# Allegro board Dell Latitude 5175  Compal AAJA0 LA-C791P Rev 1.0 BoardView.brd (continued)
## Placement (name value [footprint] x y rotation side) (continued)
Q18  AO7400_SC-70-3  [AO7404_SC70-3]  35.98 109.62 270 bottom
Q20  -  [MMBT3904WH_SOT323-3]  20.62 69.22 180 bottom
Q21  -  [MMBT3904WH_SOT323-3]  25.48 14.12 0 bottom
Q22  -  [DMP3099L-7_SOT23-3]  208.5 107.22 180 bottom
Q23  DII-DMN65D8LW-7  [SSM3K7002FU_SC70-3]  205.1 104.07 180 bottom
QA2  -  [DMN2400UV-7_SOT-563-6]  13.23 138.87 180 bottom
QT1  -  [DMN2400UV-7_SOT-563-6]  35.07 56.77 180 top
R1  10K_0201_1%  [R_0201]  208.04 143.21 90 top
R2  2.2K_0201_5%  [R_0201]  198.02 143.13 90 top
R3  100K_0201_5%  [R_0201]  198.65 143.13 90 top
R4  0_0402_5%  [R0402_0OHM]  202.67 143.14 0 top
R5  100K_0402_5%  [R_0402]  210.4 142.42 180 top
R6  0_0402_5%  [R_0402]  203.58 141.93 180 top
R7  0_0201_5%  [R_0201]  209.37 141.59 270 top
R8  0_0402_5%  [R_0402]  203.58 140.91 180 top
R9  33_0201_1%  [R_0201]  49.76 140.67 270 top
R10  10K_0402_5%  [R_0402]  48.44 139.61 90 top
R11  0_0402_5%  [R_0402]  203.56 139.87 180 top
R12  0_0201_5%  [R0201_0OHM]  49.17 139.41 0 top
R13  0_0402_5%  [R_0402]  203.56 138.98 180 top
R14  0_0201_5%  [R0201_0OHM]  210.63 138.58 90 top
R15  0_0603_5%  [R0603_0OHM]  46.63 138.5 180 top
R16  0_0402_5%  [R0402_0OHM]  194.18 138.93 270 top
R17  0_0402_5%  [R_0402]  195.07 138.93 270 top
R18  33_0201_1%  [R_0201]  49.78 138.72 270 top
R19  0_0201_5%  [R0201_0OHM]  211.21 137.89 90 top
R20  0_0201_5%  [R0201_0OHM]  210.62 137.27 90 top
R21  1K_0201_5%  [R_0201]  6.73 136.96 90 top
R22  100K_0201_5%  [R_0201]  192.81 136.48 90 top
R23  0_0402_5%  [R0402_0OHM]  191.92 136.79 270 top
R24  10K_0402_5%  [R_0402]  197.46 136.29 180 top
R25  33_0201_1%  [R_0201]  49.81 135.75 90 top
R26  10K_0201_5%  [R_0201]  57.2 135.42 90 top
R27  10K_0201_1%  [R_0201]  211.65 135.52 180 top
R28  1M_0201_5%  [R_0201]  50.04 134.83 180 top
R29  0_0402_5%  [R_0402]  206.27 135.24 270 top
R30  0_0402_5%  [R_0402]  207.16 135.24 270 top
R31  10K_0201_1%  [R_0201]  207.92 135.08 270 top
R32  0_0402_5%  [R_0402]  53.66 134.66 0 top
R33  0_0402_5%  [R_0402]  191.92 134.13 90 top
R34  100K_0201_5%  [R_0201]  48.79 134.27 90 top
R35  0_0402_5%  [R0402_0OHM]  43.23 134.38 180 top
R36  0_0603_5%  [R0603_0OHM]  56.72 134.6 270 top
R37  0_0402_5%  [R_0402]  53.66 133.8 0 top
R38  100K_0201_5%  [R_0201]  190.33 133.31 90 top
R39  0_0402_5%  [R_0402]  53.66 132.93 0 top
R40  100K_0201_5%  [R_0201]  119.93 132.34 0 top
R41  100K_0201_5%  [R_0201]  121.73 132.32 180 top
R42  100K_0201_5%  [R_0201]  149.15 132.3 180 top
R43  0_0402_5%  [R0402_0OHM]  209.6 132.3 0 top
R44  0_0402_5%  [R0402_0OHM]  147.84 132.2 180 top
R45  0_0402_5%  [R0402_0OHM]  140.18 132.18 0 top
R46  0_0402_5%  [R_0402]  53.66 132.07 0 top
R49  100K_0201_5%  [R_0201]  149.15 131.66 180 top
R50  560K_0402_5%  [R_0402]  142.13 131.59 0 top
R51  0_0201_5%  [R_0201]  209.74 131.56 0 top
R52  10K_0201_1%  [R_0201]  205.13 131.19 90 top
R53  0_0402_5%  [R0402_0OHM]  24.82 131.19 0 top
R54  10K_0402_5%  [R_0402]  26.56 131.19 0 top
R55  0_0603_5%  [R0603_0OHM]  124.46 131.16 180 top
R56  0_0402_5%  [R0402_0OHM]  120.57 131.56 270 top
R57  0_0603_5%  [R0603_0OHM]  129.86 130.8 0 top
R58  0_0603_5%  [R0603_0OHM]  145.26 129.86 90 top
R59  0_0603_5%  [R0603_0OHM]  144.06 129.85 90 top
R60  100K_0201_5%  [R_0201]  197.74 130.66 270 top
R61  10K_0201_5%  [R_0201]  198.4 130.66 270 top
R62  680_0201_5%  [R_0201]  122.31 130.04 0 top
R63  100K_0201_5%  [R_0201]  108.24 129.99 180 top
R64  8.2K_0201_1%  [R_0201]  86.42 129.96 0 top
R65  470K_0402_5%  [R_0402]  143.01 129.83 180 top
R66  10_0201_1%  [R_0201]  87.64 129.37 90 top
R67  100K_0201_5%  [R_0201]  49.12 129.34 90 top
R68  75_0402_5%  [R_0402]  191.3 129.62 180 top
R69  0_0402_5%  [R_0402]  120.13 129.57 0 top
R70  0_0402_5%  [R0402_0OHM]  30.3 129.53 180 top
R71  8.2K_0201_1%  [R_0201]  87.01 129.4 180 top
R72  1M_0402_5%  [R_0402]  137.13 128.79 180 top
R73  0_0402_5%  [R_0402]  30.3 128.64 180 top
R74  8.2K_0201_1%  [R_0201]  82.55 128.91 270 top
R75  10_0201_1%  [R_0201]  83.16 128.32 90 top
R76  8.2K_0201_1%  [R_0201]  83.77 128.32 90 top
R77  24.9_0201_1%  [R_0201]  85.75 128.69 270 top
R78  0_0402_5%  [R0402_0OHM]  113.74 127.85 90 top
R79  0_0402_5%  [R0402_0OHM]  114.76 127.85 90 top
R80  0_0402_5%  [R0402_0OHM]  115.67 127.85 90 top
R81  0_0402_5%  [R0402_0OHM]  116.69 127.85 90 top
R82  0_0402_5%  [R0402_0OHM]  117.63 127.85 90 top
R83  0_0402_5%  [R0402_0OHM]  118.64 127.85 90 top
R84  0_0201_5%  [R_0201]  140.78 128.06 180 top
R85  100K_0201_5%  [R_0201]  150.04 127.96 0 top
R86  0_0402_5%  [R0402_0OHM]  96.98 127.83 0 top
R87  0_0201_5%  [R0201_0OHM]  139.6 128.09 270 top
R88  0_0402_5%  [R_0402]  92.96 127.8 0 top
R89  0_0603_5%  [R0603_0OHM]  126.47 127.68 180 top
R93  0_0603_5%  [R0603_0OHM]  209.09 127.32 0 top
R94  100K_0201_5%  [R_0201]  140.18 126.85 90 top
R95  100K_0201_5%  [R_0201]  140.79 126.85 90 top
R96  0_0402_5%  [R0402_0OHM]  96.98 126.96 0 top
R97  0_0402_5%  [R_0402]  92.96 126.93 0 top
R98  0_0603_5%  [R0603_0OHM]  105.7 126.79 180 top
R99  8.2K_0201_5%  [R_0201]  132.93 126.79 0 top
R101  220K_0201_5%  [R_0201]  44.59 126.69 0 top
R102  24.9_0201_1%  [R_0201]  83.85 126.66 180 top
R103  100_0402_5%  [R_0402]  26.72 126.6 180 top
R104  220K_0201_5%  [R_0201]  47.28 126.58 0 top
R105  100K_0201_5%  [R_0201]  204.1 126.41 0 top
R107  0_0402_5%  [R0402_0OHM]  52.5 126.58 270 top
R108  0_0603_5%  [R0603_0OHM]  108.29 125.36 0 top
R109  0_0603_5%  [R0603_0OHM]  125.53 125.97 270 top
R110  0_0603_5%  [R0603_0OHM]  126.75 125.96 270 top
R111  100K_0201_5%  [R_0201]  204.1 125.26 0 top
R114  8.2K_0201_5%  [R_0201]  132.7 124.32 0 top
R115  0_0603_5%  [R0603_0OHM]  209.05 124.3 0 top
R116  0_0603_5%  [R0603_0OHM]  148.02 123.4 90 top
R117  0_0603_5%  [R0603_0OHM]  129.11 124.68 270 top
R118  8.2K_0201_1%  [R_0201]  90.86 123.9 270 top
R119  8.2K_0201_1%  [R_0201]  91.44 123.32 90 top
R120  4.99_0402_1%  [R_0402]  87.91 123.03 90 top
R121  0_0402_5%  [R0402_0OHM]  54.33 123.64 270 top
R123  0_0603_5%  [R0603_0OHM]  146.82 123.01 180 top
R124  1K_0201_5%  [R_0201]  7.54 122.75 180 top
R125  24.9_0201_1%  [R_0201]  89.51 122.05 90 top
R126  0_0402_5%  [R_0402]  127.81 121.4 90 top
R132  10K_0402_5%  [R_0402]  213.22 120.35 270 top
R133  10K_0402_5%  [R_0402]  210.51 120.34 270 top
R134  10K_0402_5%  [R_0402]  211.43 120.34 270 top
R135  10K_0402_5%  [R_0402]  212.32 120.34 270 top
R136  10K_0402_5%  [R_0402]  214.13 120.34 270 top
R137  10K_0402_5%  [R_0402]  208.6 120.32 270 top
R138  10K_0402_5%  [R_0402]  209.61 120.32 270 top
R139  0_0402_5%  [R_0402]  124.07 117.87 90 top
R140  0_0402_5%  [R0402_0OHM]  28.93 114.76 0 top
R141  0_0402_5%  [R_0402]  28.93 113.85 0 top
R142  0_0603_5%  [R0603_0OHM]  24.79 112.61 90 top
R143  0_0402_5%  [R0402_0OHM]  30.82 113.1 0 top
R144  100K_0201_5%  [R_0201]  29.98 111.8 180 top
R145  100K_0201_5%  [R_0201]  29.98 111.24 180 top
R146  10K_0402_5%  [R_0402]  214.87 110.95 270 top
R147  10K_0402_5%  [R_0402]  215.86 110.95 270 top
R148  10K_0402_5%  [R_0402]  216.85 110.95 270 top
R149  0_0603_5%  [R0603_0OHM]  25.07 110.3 180 top
R150  220K_0201_5%  [R_0201]  117.06 109.29 180 top
R151  10K_0402_5%  [R_0402]  213.86 108.24 90 top
R152  10K_0402_5%  [R_0402]  214.87 108.21 90 top
R153  10K_0402_5%  [R_0402]  215.86 108.21 90 top
R154  10K_0402_5%  [R_0402]  216.85 108.21 90 top
R155  100K_0201_5%  [R_0201]  150.29 107.48 0 top
R156  10K_0201_5%  [R_0201]  139.78 107.39 270 top
R157  10K_0201_5%  [R_0201]  140.33 107.39 270 top
R158  10K_0201_5%  [R_0201]  140.97 107.39 270 top
R159  10K_0201_5%  [R_0201]  141.6 107.39 270 top
R160  0_0603_5%  [R0603_0OHM]  37.29 106.3 90 top
R161  0_0603_5%  [R0603_0OHM]  34.34 106.28 90 top
R162  100K_0201_5%  [R_0201]  215.8 106.89 270 top
R163  0_0402_5%  [R0402_0OHM]  131.19 105.81 180 top
R164  0_0402_5%  [R0402_0OHM]  170.54 105.7 0 top
R165  0_0603_5%  [R0603_0OHM]  46.55 104.87 180 top
R166  0_0402_5%  [R_0402]  196.99 104.6 270 top
R167  100K_0201_5%  [R_0201]  51.93 103.57 180 top
R168  220K_0201_5%  [R_0201]  102.81 102.8 90 top
R169  100K_0201_5%  [R_0201]  51.93 102.99 180 top
R170  0_0402_5%  [R_0402]  77.24 102.61 180 top
R171  0_0402_5%  [R0402_0OHM]  68.76 102.33 0 top
R172  10K_0201_5%  [R_0201]  137.52 102.03 90 top
R173  10K_0201_5%  [R_0201]  138.1 102.03 90 top
R174  0_0603_5%  [R0603_0OHM]  151.76 102.85 270 top
R175  0_0402_5%  [R_0402]  51.98 101.58 180 top
R176  0_0402_5%  [R0402_0OHM]  68.76 101.44 0 top
R177  0_0402_5%  [R_0402]  212.42 101.39 0 top
R178  0_0402_5%  [R_0402]  76.35 101.72 270 top
R179  100K_0201_5%  [R_0201]  36.98 100.85 90 top
R180  0_0402_5%  [R_0402]  35.36 100.68 90 top
R181  0_0402_5%  [R0402_0OHM]  36.25 100.68 90 top
R182  0_0603_5%  [R0603_0OHM]  136.82 101.13 0 top
R183  0_0603_5%  [R0603_0OHM]  47.23 101.08 0 top
R184  100K_0201_5%  [R_0201]  77.09 101.37 270 top
R185  0_0402_5%  [R_0402]  51.98 100.72 180 top
R186  100K_0201_5%  [R_0201]  69.2 100.7 0 top
R187  0_0603_5%  [R0603_0OHM]  211.1 101.32 270 top
R188  10K_0402_5%  [R_0402]  212.42 100.5 0 top
R189  0_0402_5%  [R_0402]  202.59 100.5 270 top
R190  0_0201_5%  [R0201_0OHM]  181.51 99.99 0 top
R191  0_0201_5%  [R0201_0OHM]  181.51 99.35 0 top
R192  0_0603_5%  [R0603_0OHM]  213.26 99.49 270 top
R193  0_0402_5%  [R0402_0OHM]  195.61 98.72 0 top
R194  0_0201_5%  [R0201_0OHM]  170.9 98.62 0 top
R195  100K_0402_5%  [R_0402]  209.07 98.97 270 top
R196  0_0402_5%  [R_0402]  210.08 98.97 270 top
R197  10K_0402_5%  [R_0402]  210.97 98.97 270 top
R198  100K_0402_5%  [R_0402]  214.3 98.95 270 top
R199  100K_0402_5%  [R_0402]  215.19 98.95 270 top
R200  100K_0402_5%  [R_0402]  216.08 98.95 270 top
R201  0_0201_5%  [R0201_0OHM]  170.9 98.01 0 top
R202  10K_0402_5%  [R_0402]  25.09 82.18 0 top
R203  10K_0402_5%  [R_0402]  26.9 82.18 0 top
R204  10K_0402_5%  [R_0402]  25.09 81.19 0 top
R205  10K_0402_5%  [R_0402]  26.87 81.19 0 top
R206  10K_0402_5%  [R_0402]  25.09 80.2 0 top
R207  10K_0402_5%  [R_0402]  26.87 80.2 0 top
R208  10K_0402_5%  [R_0402]  25.09 79.26 0 top
R209  4.99K_0201_1%  [R_0201]  27.89 78.84 90 top
R210  100K_0201_5%  [R_0201]  41.95 76.09 0 top
R212  100K_0402_5%  [R_0402]  25.12 70.3 90 top
R213  10K_0402_5%  [R_0402]  26.7 70.3 90 top
R214  10K_0402_5%  [R_0402]  27.56 70.3 90 top
R217  0_0603_5%  [R0603_0OHM]  37.3 71.1 180 top
R218  4.7K_0402_5%  [R_0402]  43.74 64.73 180 top
R219  4.7K_0402_5%  [R_0402]  34.82 64.68 270 top
R220  0_0402_5%  [R_0402]  43.74 63.85 180 top
R221  4.7K_0402_5%  [R_0402]  43.74 62.96 180 top
R222  4.7K_0402_5%  [R_0402]  33.93 62.85 0 top
R223  4.7K_0402_5%  [R_0402]  33.06 62.87 270 top
R224  4.7K_0402_5%  [R_0402]  43.74 62.07 180 top
R225  4.7K_0402_5%  [R_0402]  33.93 61.94 0 top
R226  4.7K_0402_5%  [R_0402]  43.74 61.18 180 top
R227  4.7K_0402_5%  [R_0402]  33.93 61.04 0 top
R228  4.7K_0402_5%  [R_0402]  43.74 60.29 180 top
R229  4.7K_0402_5%  [R_0402]  33.93 60.15 0 top
R230  4.7K_0402_5%  [R_0402]  43.74 59.4 180 top
R231  0_0402_5%  [R0402_0OHM]  33.93 59.26 0 top
R232  4.7K_0402_5%  [R_0402]  43.74 58.51 180 top
R233  0_0201_5%  [R_0201]  34.56 58.26 0 top
R234  0_0201_5%  [R_0201]  36.39 58.26 180 top
R235  4.99K_0201_1%  [R_0201]  37.61 57.77 270 top
R236  0_0201_5%  [R0201_0OHM]  38.2 57.19 90 top
R237  0_0201_5%  [R0201_0OHM]  38.77 57.19 90 top
R238  100K_0201_5%  [R_0201]  35.24 57.51 180 top
R239  4.7K_0201_5%  [R_0201]  43.41 56.96 180 top
R240  100K_0402_5%  [R_0402]  26.94 66.25 0 top
R241  1M_0402_5%  [R_0402]  29.6 66.25 180 top
R242  0_0402_5%  [R0402_0OHM]  32.99 48.26 90 top
R243  10K_0402_5%  [R_0402]  31.38 64.9 180 top
R244  4.7K_0201_5%  [R_0201]  35.6 54.27 270 top
R245  100K_0402_5%  [R_0402]  23.71 60.95 90 top
R246  4.7K_0201_5%  [R_0201]  43.21 50.95 0 top
R247  100K_0402_5%  [R_0402]  39.8 50.82 180 top
R248  0_0402_5%  [R_0402]  22.82 60.95 90 top
R249  22.1K_0402_1%  [R_0402]  30.81 61.8 0 top
R250  0_0201_5%  [R0201_0OHM]  37.58 50.49 0 top
R251  4.7K_0201_5%  [R_0201]  43.21 50.39 0 top
R252  0_0402_5%  [R_0402]  21.93 60.95 90 top
R253  10K_0402_5%  [R_0402]  42.42 49.7 180 top
R254  0_0402_5%  [R0402_0OHM]  35.08 47.74 270 top
R255  0_0402_5%  [R0402_0OHM]  40.3 48.73 90 top
R256  93.1K_0402_1%  [R_0402]  38.53 48.72 90 top
R257  0_0402_5%  [R0402_0OHM]  39.42 48.72 90 top
R258  15K_0402_1%  [R_0402]  36.7 48.7 90 top
R259  0_0402_5%  [R_0402]  37.58 48.7 90 top
R260  0_0402_5%  [R_0402]  35.82 48.7 90 top
R261  10K_0402_5%  [R_0402]  29.62 42.34 270 top
R262  10K_0402_5%  [R_0402]  30.51 41.43 90 top
R263  10K_0402_5%  [R_0402]  42.42 48.81 180 top
R264  0_0402_5%  [R0402_0OHM]  30.52 40.55 180 top
R265  0_0402_5%  [R0402_0OHM]  31.81 46.65 270 top
R266  0_0402_5%  [R0402_0OHM]  32.7 46.65 270 top
R267  4.7K_0201_5%  [R_0201]  42.15 44.9 180 top
R268  10K_0402_5%  [R_0402]  39.49 45.19 270 top
R269  0_0402_5%  [R0402_0OHM]  29.67 45.28 270 top
R270  0_0402_5%  [R0402_0OHM]  30.53 45.28 270 top
R271  4.7K_0201_5%  [R_0201]  42.15 45.48 180 top
R272  4.7K_0201_5%  [R_0201]  32.49 44.05 90 top
R273  4.7K_0201_5%  [R_0201]  31.71 44.03 90 top
R274  0_0402_5%  [R_0402]  42.01 44.14 180 top
R275  10K_0402_5%  [R_0402]  43.08 45.07 270 top
R276  0_0402_5%  [R_0402]  29.6 39.66 0 top
R277  0_0402_5%  [R_0402]  29.6 38.78 0 top
R278  0_0402_5%  [R0402_0OHM]  32.26 41.75 0 top
R279  0_0402_5%  [R_0402]  30.52 37.89 180 top
R280  0_0402_5%  [R0402_0OHM]  32.26 40.86 0 top
R281  0_0402_5%  [R0402_0OHM]  31.39 40.3 90 top
R282  1K_0201_5%  [R_0201]  32.42 40.12 0 top
R283  0_0402_5%  [R_0402]  30.52 37 180 top
R284  0_0402_5%  [R0402_0OHM]  31.39 39.42 270 top
R285  10K_0402_5%  [R_0402]  21.93 35.18 270 top
R286  10K_0402_5%  [R_0402]  22.8 35.18 270 top
R295  10K_0402_5%  [R_0402]  21.93 33.45 270 top
R296  10K_0402_5%  [R_0402]  22.8 33.45 270 top
R297  0_0402_5%  [R_0402]  37.31 36.2 270 top
R298  10K_0402_5%  [R_0402]  38.2 36.2 270 top
R299  0_1206_5%  [R1206_0OHM]  42.57 33.54 90 top
R300  0_0402_5%  [R_0402]  39.34 34.3 90 top
R301  0_0402_5%  [R0402_0OHM]  36.98 34.38 0 top
R302  0_0402_5%  [R0402_0OHM]  39.97 33.37 0 top
R303  0_0402_5%  [R_0402]  38.87 33.14 270 top
R304  0_0201_5%  [R0201_0OHM]  21.89 30.99 270 top
R305  0_0201_5%  [R0201_0OHM]  22.45 30.99 270 top
R306  0_0201_5%  [R0201_0OHM]  23.32 30.41 90 top
R307  0_0201_5%  [R0201_0OHM]  23.88 30.41 90 top
R308  0_0402_5%  [R_0402]  36.41 30.39 0 top
R309  10K_0201_5%  [R_0201]  188.87 142.46 90 bottom
R310  10K_0201_5%  [R_0201]  187.35 142.46 90 bottom
R311  10K_0201_5%  [R_0201]  186.74 142.46 90 bottom
R312  10K_0201_5%  [R_0201]  191.36 142.45 90 bottom
R313  10K_0201_5%  [R_0201]  190.68 142.45 90 bottom
R314  10K_0201_5%  [R_0201]  190.09 142.45 90 bottom
R315  10K_0201_5%  [R_0201]  189.51 142.45 90 bottom
R316  10K_0201_5%  [R_0201]  186.16 143.03 270 bottom
R317  49.9_0402_1%  [R_0402]  188.11 142.05 90 bottom
R318  10K_0201_5%  [R_0201]  193.29 140.49 90 bottom
R319  2.2K_0201_5%  [R_0201]  192.61 140.49 90 bottom
R320  2.2K_0201_5%  [R_0201]  190.32 140.49 90 bottom
R321  2.2K_0201_5%  [R_0201]  189.61 140.49 90 bottom
R322  2.2K_0201_5%  [R_0201]  191.77 140.46 90 bottom
R323  2.2K_0201_5%  [R_0201]  191.01 140.46 90 bottom
R324  SHORT PADS  [SHORTPADS]  187.73 140.48 90 bottom
R325  0_0201_5%  [R_0201]  198.5 140.72 270 bottom
R326  0_0402_5%  [R0402_0OHM]  186.66 139.46 90 bottom
R327  43_0201_5%  [R_0201]  185.93 139.63 90 bottom
R328  2.2K_0201_5%  [R_0201]  192.61 139.27 90 bottom
R329  100K_0201_5%  [R_0201]  189.59 139.85 270 bottom
R330  2.2K_0201_5%  [R_0201]  191.77 139.25 90 bottom
R331  2.2K_0201_5%  [R_0201]  190.91 139.25 90 bottom
R332  10K_0201_5%  [R_0201]  190.27 139.25 90 bottom
R333  0_0201_5%  [R_0201]  198.88 139.51 270 bottom
R334  100K_0201_5%  [R_0201]  198.17 138.92 90 bottom
R335  1.5K_0201_1%  [R_0201]  185.35 136.83 180 bottom
R336  10K_0201_5%  [R_0201]  185.36 136.08 180 bottom
R337  0_0402_5%  [R_0402]  196.44 135.78 0 bottom
R338  100K_0201_5%  [R_0201]  199.01 135.28 90 bottom
R339  10K_0201_5%  [R_0201]  185.36 135.5 180 bottom
R340  4.3K_0402_5%  [R_0402]  198.27 134.84 90 bottom
R341  240_0201_1%  [R_0201]  74.21 134.81 180 bottom
R342  100K_0201_5%  [R_0201]  185.36 134.31 180 bottom
R343  100K_0201_5%  [R_0201]  186.52 134.28 0 bottom
R344  10K_0201_5%  [R_0201]  184.77 133.67 0 bottom
R345  10K_0201_5%  [R_0201]  187.13 133.39 180 bottom
R346  10K_0201_5%  [R_0201]  185.32 133.05 270 bottom
R347  10K_0201_5%  [R_0201]  197.62 132.63 0 bottom
R348  0_0402_5%  [R_0402]  186.38 132.25 0 bottom
R349  0_0402_5%  [R0402_0OHM]  186.38 131.36 0 bottom
R350  0_0603_5%  [R_0603]  197.92 130.46 90 bottom
R351  0.01_0603_1%  [R_0603]  196.7 130.46 90 bottom
R352  2.2K_0201_5%  [R_0201]  185.48 130.57 180 bottom
R353  100K_0201_5%  [R_0201]  186.55 130.55 0 bottom
R354  100K_0201_5%  [R_0201]  184.9 129.96 0 bottom
R355  0_0402_5%  [R0402_0OHM]  192.76 129.28 90 bottom
R356  10_0402_1%  [R_0402]  191.74 130.19 270 bottom
R357  10K_0201_5%  [R_0201]  198.93 129.68 180 bottom
R358  0_0402_5%  [R0402_0OHM]  48.39 129.68 180 bottom
R359  100K_0201_5%  [R_0201]  190.07 129.95 270 bottom
R360  100K_0201_5%  [R_0201]  189.08 129.36 90 bottom
R361  100K_0201_5%  [R_0201]  188.37 129.36 90 bottom
R362  100K_0201_5%  [R_0201]  187.76 129.95 270 bottom
R363  2.2K_0201_5%  [R_0201]  187.12 129.95 270 bottom
R364  0_0402_5%  [R0402_0OHM]  25.32 128.69 90 bottom
R365  240_0201_1%  [R_0201]  68.12 128.74 0 bottom
R366  0_0402_5%  [R0402_0OHM]  198.58 128.06 90 bottom
R367  240_0201_1%  [R_0201]  81.87 128.19 90 bottom
R369  10K_0201_5%  [R_0201]  196.57 126.85 180 bottom
R374  0_0402_5%  [R0402_0OHM]  134.45 125.35 90 bottom
R375  0_0402_5%  [R0402_0OHM]  133.44 125.35 90 bottom
R376  0_0402_5%  [R0402_0OHM]  139.76 125.34 90 bottom
R377  0_0402_5%  [R0402_0OHM]  138.75 125.34 90 bottom
R378  0_0402_5%  [R0402_0OHM]  145.88 125.34 90 bottom
R379  0_0402_5%  [R0402_0OHM]  144.89 125.34 90 bottom
R380  0_0402_5%  [R0402_0OHM]  143.87 125.34 90 bottom
R381  0_0402_5%  [R0402_0OHM]  142.85 125.34 90 bottom
R382  0_0402_5%  [R0402_0OHM]  141.71 125.34 90 bottom
R383  0_0402_5%  [R0402_0OHM]  140.69 125.34 90 bottom
R387  1K_0201_5%  [R_0201]  48.06 122.99 180 bottom
R388  0_0402_5%  [R0402_0OHM]  24.83 121.91 0 bottom
R389  10K_0201_5%  [R_0201]  14.88 121.97 270 bottom
R391  0_0402_5%  [R0402_0OHM]  171.93 121.3 0 bottom
R392  240_0201_1%  [R_0201]  90.45 120.8 270 bottom
R394  0_0402_5%  [R0402_0OHM]  209.58 119.37 0 bottom
R395  100K_0201_5%  [R_0201]  203.36 119.22 0 bottom
R398  0_0402_5%  [R0402_0OHM]  209.58 118.53 0 bottom
R400  0_0402_5%  [R0402_0OHM]  204.9 114.62 90 bottom
R403  0_0402_5%  [R0402_0OHM]  30.63 110.63 270 bottom
R404  0_0402_5%  [R0402_0OHM]  29.36 110.63 270 bottom
R406  0_0603_5%  [R_0603]  34.77 110.29 270 bottom
R407  10K_0402_5%  [R_0402]  28.47 109.74 270 bottom
R408  0_0402_5%  [R_0402]  27.58 108.83 90 bottom
R409  0_0402_5%  [R_0402]  26.7 108.83 90 bottom
R410  10K_0201_5%  [R_0201]  117.86 108.54 90 bottom
R411  100_0402_5%  [R_0402]  194.54 108.35 90 bottom
R412  0_0402_5%  [R0402_0OHM]  89.66 108.65 180 bottom
R416  220K_0201_5%  [R_0201]  112.84 107.1 180 bottom
R417  330_0603_5%  [R_0603]  116.24 106.8 180 bottom
R419  220K_0201_5%  [R_0201]  113.01 105.87 90 bottom
R421  0_0603_5%  [R0603_0OHM]  114.85 105.58 0 bottom
R423  1K_0402_1%  [R_0402]  78.26 104.51 90 bottom
R425  0_0603_5%  [R0603_0OHM]  177.58 104.84 180 bottom
R432  0_0603_5%  [R0603_0OHM]  175.48 103.51 180 bottom
R433  4.7K_0201_5%  [R_0201]  54.36 103.56 270 bottom
R434  4.7K_0201_5%  [R_0201]  53.8 103.56 270 bottom
R435  4.99K_0201_1%  [R_0201]  59.18 102.9 90 bottom
R436  100K_0402_5%  [R_0402]  180.3 102.2 90 bottom
R437  0_0402_5%  [R_0402]  70.08 102 180 bottom
R438  0_0603_5%  [R0603_0OHM]  63.48 100.67 90 bottom
R439  4.7K_0201_5%  [R_0201]  48.73 101.29 0 bottom
R440  4.7K_0201_5%  [R_0201]  47.41 101.29 0 bottom
R441  0_0402_5%  [R0402_0OHM]  72.72 101.13 0 bottom
R442  0_0402_5%  [R0402_0OHM]  70.08 101.11 180 bottom
R443  4.7K_0201_5%  [R_0201]  48.73 100.7 0 bottom
R444  4.7K_0201_5%  [R_0201]  47.41 100.7 0 bottom
R445  0_0402_5%  [R0402_0OHM]  66.28 100.66 0 bottom
R446  4.7K_0201_5%  [R_0201]  47.41 99.91 0 bottom
R447  100K_0201_5%  [R_0201]  62.89 99.32 90 bottom
R448  4.7K_0201_5%  [R_0201]  48.6 99.18 0 bottom
R449  4.7K_0201_5%  [R_0201]  47.41 99.18 0 bottom
R450  0_0201_5%  [R0201_0OHM]  61.1 98.75 0 bottom
R451  4.7K_0201_5%  [R_0201]  47.4 98.45 0 bottom
R452  4.7K_0201_5%  [R_0201]  48.6 98.44 0 bottom
R453  2.2K_0402_5%  [R_0402]  63.04 98.59 270 bottom
R454  0_0201_5%  [R0201_0OHM]  61.1 97.98 0 bottom
R455  100K_0201_5%  [R_0201]  62.31 97.44 90 bottom
R456  4.7K_0201_5%  [R_0201]  48.58 97.53 0 bottom
R457  4.7K_0201_5%  [R_0201]  47.38 97.53 0 bottom
R458  100K_0201_5%  [R_0201]  61.44 96.55 90 bottom
R459  2.2K_0402_5%  [R_0402]  62.15 96.69 0 bottom
R460  4.7K_0201_5%  [R_0201]  48.58 96.59 0 bottom
R461  4.7K_0201_5%  [R_0201]  47.38 96.59 0 bottom
R462  0_0201_5%  [R0201_0OHM]  62.27 95.75 0 bottom
R463  1K_0402_5%  [R_0402]  71.53 95.27 90 bottom
R464  0_0402_5%  [R0402_0OHM]  68.02 95.27 90 bottom
R465  0_0402_5%  [R0402_0OHM]  65.63 95.27 90 bottom
R466  100K_0201_5%  [R_0201]  61.59 95.79 270 bottom
R467  0_0201_5%  [R0201_0OHM]  62.27 95.19 0 bottom
R468  1M_0201_5%  [R_0201]  58.28 95.14 0 bottom
R469  1M_0201_5%  [R_0201]  54.19 95.14 180 bottom
R470  0_0402_5%  [R0402_0OHM]  20.42 90.02 0 bottom
R471  0_0402_5%  [R_0402]  19.56 90.02 180 bottom
R472  0_0402_5%  [R_0402]  21.28 40.12 270 bottom
R473  0_0402_5%  [R_0402]  20.42 40.12 270 bottom
R474  0_0402_5%  [R0402_0OHM]  19.46 40.12 270 bottom
R475  0_0402_5%  [R0402_0OHM]  18.57 40.12 270 bottom
R476  0_0402_5%  [R0402_0OHM]  20.87 29.3 90 bottom
R477  0_0402_5%  [R0402_0OHM]  19.98 29.3 90 bottom
R478  0_0201_5%  [R0201_0OHM]  34.65 44.8 270 top
R479  0_0201_5%  [R0201_0OHM]  34.09 44.8 270 top
R480  0_0201_5%  [R0201_0OHM]  129.18 126.66 180 bottom
R481  0_0201_5%  [R0201_0OHM]  129.18 126 180 bottom
R482  0_0201_5%  [R_0201]  63.45 95.13 90 bottom
R483  100K_0201_5%  [R_0201]  204.72 124.63 180 top
R484  0_0402_5%  [R_0402]  41.49 46.21 0 top
R485  0_0402_5%  [R_0402]  36.41 29.5 0 top
R486  10K_0402_5%  [R_0402]  42.42 47.08 180 top
R487  10K_0402_5%  [R_0402]  42.42 47.95 180 top
R488  0_0201_5%  [R_0201]  41.16 50.43 0 top
R489  0_0201_5%  [R_0201]  40.22 48.01 0 top
R490  0_0201_5%  [R_0201]  43.22 43.42 180 top
R491  0_0201_5%  [R_0201]  40.2 46.84 0 top
R492  0_0201_5%  [R_0201]  40.22 47.42 0 top
R493  0_0201_5%  [R_0201]  43.81 43.44 90 top
R494  0_0402_5%  [R0402_0OHM]  198.46 141.51 90 bottom
R495  0_0402_5%  [R0402_0OHM]  32.36 57.57 180 top
R496  0_0402_5%  [R_0402]  40.68 46.08 180 top
R497  0_0603_5%  [R0603_0OHM]  208.81 111.29 270 top
R498  100K_0402_5%  [R_0402]  200.69 134.08 90 top
R499  200K_0402_1%  [R_0402]  204.11 107.72 90 bottom
R500  36.5K_0402_1%  [R_0402]  204.11 109.5 90 bottom
R501  499_0402_1%  [R_0402]  211.72 103.55 0 top
R502  499_0402_1%  [R_0402]  212.23 104.43 0 top
R511  0.01_0603_1%  [R_0603]  209.38 112.42 270 bottom
R512  0.01_0603_1%  [R_0603]  208.94 105.36 0 bottom
R513  1M_0402_5%  [R_0402]  208.36 111.01 180 bottom
R514  100K_0402_5%  [R_0402]  203.44 105.65 270 bottom
R515  0.01_0603_1%  [R_0603]  206.92 105.04 90 bottom
RA1  2.2K_0201_5%  [R_0201]  8.94 144.63 270 top
RA2  1K_0201_5%  [R_0201]  6.69 141.7 0 top
RA3  2.2K_0201_5%  [R_0201]  9.14 139.75 0 top
RA4  6.8_0402_5%  [R_0402]  6.6 139.99 0 top
RA9  10K_0201_5%  [R_0201]  20.35 131.7 90 top
RA10  0_0201_5%  [R0201_0OHM]  20.9 132.29 270 top
RA11  0_0402_5%  [R0402_0OHM]  21.64 132.17 270 top
RA12  0_0201_5%  [R0201_0OHM]  22.38 132.29 270 top
RA13  0_0402_5%  [R0402_0OHM]  23.11 132.17 270 top
RA14  0_0201_5%  [R0201_0OHM]  23.85 132.29 270 top
RA15  0_0201_5%  [R_0201]  8.83 131.61 0 top
RA16  0_0201_5%  [R0201_0OHM]  9.41 131.02 180 top
RA17  10K_0201_5%  [R_0201]  20.35 130.48 90 top
RA18  0_0402_5%  [R0402_0OHM]  20.43 127.78 270 top
RA19  0_0402_5%  [R0402_0OHM]  9.86 121.65 180 top
RA20  75_0402_5%  [R_0402]  142.32 106.85 0 top
RA21  0_0402_5%  [R_0402]  144.98 105.97 180 top
RA22  0_0402_5%  [R0402_0OHM]  144.98 105.07 180 top
RA23  0_0402_5%  [R_0402]  136.65 104.89 270 top
RA24  0_0402_5%  [R0402_0OHM]  144.07 104.18 0 top
RA25  0_0402_5%  [R0402_0OHM]  144.07 103.29 0 top
RA26  0_0402_5%  [R0402_0OHM]  136.68 102.2 90 top
RA27  0_0402_5%  [R0402_0OHM]  144.98 102.4 180 top
RA28  0_0402_5%  [R_0402]  146.74 101.54 180 top
RA29  75_0402_5%  [R_0402]  144.02 100.88 0 top
RA30  100K_0201_5%  [R_0201]  28.89 88.22 0 top
RA31  2.2K_0201_5%  [R_0201]  35.89 85.63 90 top
RA32  0_0201_5%  [R0201_0OHM]  36.47 85.63 90 top
RA33  0_0201_5%  [R0201_0OHM]  37.03 85.63 90 top
RA34  0_0201_5%  [R0201_0OHM]  37.62 85.63 90 top
RA35  0_0201_5%  [R0201_0OHM]  38.2 85.63 90 top
RA36  2.2K_0201_5%  [R_0201]  38.79 85.63 90 top
RA37  10K_0201_5%  [R_0201]  30.63 83.57 90 top
RA38  10K_0201_5%  [R_0201]  31.27 84.15 270 top
RA39  10K_0201_5%  [R_0201]  37.44 76.9 180 top
RA40  1K_0201_5%  [R_0201]  10.39 142.7 270 bottom
RA42  6.8_0402_5%  [R_0402]  9.7 141.9 180 bottom
RA43  100K_0402_1%  [R_0402]  17.23 140.74 90 bottom
RA44  100K_0402_1%  [R_0402]  16.33 138.98 0 bottom
RA45  0_0201_5%  [R0201_0OHM]  13.46 141.33 90 bottom
RA46  200K_0402_1%  [R_0402]  16.33 139.87 0 bottom
RA47  0_0402_5%  [R0402_0OHM]  20.85 131.13 270 bottom
RA48  0_0402_5%  [R0402_0OHM]  19.99 131.43 270 bottom
RA49  1K_0201_5%  [R_0201]  19.28 131.02 270 bottom
RA50  0_0201_5%  [R0201_0OHM]  22.3 129.87 270 bottom
RA51  0_0201_5%  [R_0201]  21.59 130.99 270 bottom
RA52  100K_0201_5%  [R_0201]  20.59 128.6 180 bottom
RA53  100K_0402_1%  [R_0402]  20.29 127.49 180 bottom
RA54  64.9K_0402_1%  [R_0402]  22.14 126.91 180 bottom
RA55  33_0201_1%  [R_0201]  16.57 124.75 180 bottom
RA56  0_0603_5%  [R0603_0OHM]  16.62 123 180 bottom
RA57  47K_0201_5%  [R_0201]  16.65 121.99 180 bottom
RA58  0_0402_5%  [R_0402]  9.98 122.42 270 bottom
RA59  47K_0201_5%  [R_0201]  15.47 121.39 90 bottom
RA60  0.1_0805_1%  [R_0805]  20.82 87.57 180 bottom
RA61  0_0402_5%  [R0402_0OHM]  8.15 128.22 90 top
RA62  0_0402_5%  [R0402_0OHM]  8.85 121.49 90 bottom
RA63  0_0402_5%  [R0402_0OHM]  6.79 132.82 0 top
RA64  0_0201_5%  [R_0201]  13.8 138.12 180 bottom
RA65  0_0201_5%  [R_0201]  12.86 141.32 180 bottom
RC1  0_0402_5%  [R0402_0OHM]  50.52 142.36 0 top
RC2  0_0402_5%  [R0402_0OHM]  55.45 142.36 180 top
RC3  0_0402_5%  [R0402_0OHM]  44.6 141.39 90 top
RC4  0_0402_5%  [R0402_0OHM]  45.49 141.39 90 top
RC5  0_0402_5%  [R0402_0OHM]  47.27 141.39 90 top
RC6  0_0402_5%  [R0402_0OHM]  48.67 141.39 90 top
RC7  0_0402_5%  [R0402_0OHM]  49.56 141.39 90 top
RC8  0_0402_5%  [R0402_0OHM]  46.38 142.28 270 top
RC9  0_0201_5%  [R_0201]  57.21 129.96 180 top
RC10  0_0201_5%  [R_0201]  56.64 129.4 0 top
RC11  150K_0402_5%  [R_0402]  47.65 124.37 90 top
RC12  150K_0402_5%  [R_0402]  47.14 123.13 0 top
RC13  33_0201_1%  [R_0201]  44.07 122.52 0 top
RC14  100K_0201_5%  [R_0201]  81.48 122.32 180 top
RC16  0_0402_5%  [R0402_0OHM]  46.43 122.09 0 top
RC17  0_0603_5%  [R0603_0OHM]  54.45 121.12 0 top
RC18  0_0603_5%  [R0603_0OHM]  54.5 118.23 0 top
RC19  0_0603_5%  [R0603_0OHM]  55.13 115.23 0 top
RC20  100_0201_1%  [R_0201]  68.58 111.2 90 top
RC21  100_0201_1%  [R_0201]  69.19 111.2 90 top
RC22  100_0201_1%  [R_0201]  69.77 111.2 90 top
RC23  100_0201_1%  [R_0201]  70.36 111.2 90 top
RC24  0_0603_5%  [R0603_0OHM]  55.14 109.64 0 top
RC25  15_0402_5%  [R_0402]  53.14 109.11 0 top
RC26  0_0603_5%  [R0603_0OHM]  55.14 108.37 0 top
RC27  15_0402_5%  [R_0402]  53.14 108.22 0 top
RC28  15_0402_5%  [R_0402]  53.14 107.33 0 top
RC29  0_0603_5%  [R0603_0OHM]  55.16 106.87 0 top
RC30  15_0402_5%  [R_0402]  53.14 106.42 0 top
RC31  15_0402_5%  [R_0402]  53.14 105.55 0 top
RC32  15_0402_5%  [R_0402]  53.14 104.66 0 top
RC33  0_0402_5%  [R0402_0OHM]  95.61 103.6 270 top
RC34  0_0201_5%  [R_0201]  89.41 101.5 270 top
RC35  49.9_0201_1%  [R_0201]  58.1 128.06 180 bottom
RC36  49.9_0201_1%  [R_0201]  56.92 127.46 90 bottom
RC37  0_0402_5%  [R0402_0OHM]  52.88 126.91 180 bottom
RC38  10K_0201_5%  [R_0201]  51.09 124.15 180 bottom
RC39  200_0402_1%  [R_0402]  55.96 123.87 0 bottom
RC40  0_0603_5%  [R0603_0OHM]  54.91 124.31 270 bottom
RC41  200_0402_1%  [R_0402]  55.96 122.98 0 bottom
RC42  100K_0201_5%  [R_0201]  55.68 121.54 90 bottom
RC43  1K_0201_5%  [R_0201]  16.65 121.38 180 bottom
RC44  0_0603_5%  [R0603_0OHM]  55.79 120.49 0 bottom
RC45  80.6_0402_1%  [R_0402]  83.97 120.39 270 bottom
RC46  200_0402_1%  [R_0402]  83.08 120.39 270 bottom
RC47  162_0402_1%  [R_0402]  82.19 120.39 270 bottom
RC48  0_0603_5%  [R0603_0OHM]  55.79 119.22 0 bottom
RC49  33_0201_1%  [R_0201]  48.01 117.58 270 bottom
RC50  0_0603_5%  [R0603_0OHM]  55.65 116.63 0 bottom
RC51  0_0603_5%  [R0603_0OHM]  55.65 115.38 0 bottom
RC52  2.2K_0201_5%  [R_0201]  53.72 114.94 270 bottom
RC53  2.2K_0201_5%  [R_0201]  53.14 114.94 270 bottom
RC54  49.9K_0201_1%  [R_0201]  56.03 113.6 90 bottom
RC55  49.9K_0201_1%  [R_0201]  55.47 113.6 90 bottom
RC56  100_0201_1%  [R_0201]  84.61 114.12 270 bottom
RC57  100_0201_1%  [R_0201]  85.24 112.65 90 bottom
RC58  49.9K_0201_1%  [R_0201]  53.25 112.56 0 bottom
RC59  49.9K_0201_1%  [R_0201]  53.25 111.98 0 bottom
RC60  49.9K_0201_1%  [R_0201]  53.25 111.39 0 bottom
RC61  113_0402_1%  [R_0402]  55.63 110.81 180 bottom
RC62  49.9K_0201_1%  [R_0201]  53.25 110.81 0 bottom
RC63  1K_0201_5%  [R_0201]  86.18 107.85 270 bottom
RC64  0_0402_5%  [R_0402]  84.51 107.18 0 bottom
RC65  100_0201_1%  [R_0201]  64.36 106.68 90 bottom
RC66  100_0201_1%  [R_0201]  63.78 107.27 270 bottom
RC67  0_0402_5%  [R0402_0OHM]  68.4 106.31 90 bottom
RC68  0_0402_5%  [R0402_0OHM]  66.34 106.31 90 bottom
RC69  51_0402_5%  [R_0402]  73.69 106.14 90 bottom
RC70  24.9_0402_1%  [R_0402]  75.13 107.03 270 bottom
RC71  0_0201_5%  [R_0201]  72.17 106.42 0 bottom
RC72  60.4_0402_1%  [R_0402]  85.42 106.26 180 bottom
RC73  100K_0201_5%  [R_0201]  62.05 105.79 90 bottom
RC74  100K_0201_5%  [R_0201]  61.49 105.79 90 bottom
RC75  0_0201_5%  [R_0201]  82.3 106.28 270 bottom
RC76  100K_0201_5%  [R_0201]  53.38 105.91 180 bottom
RC77  1K_0402_5%  [R_0402]  83.03 105.25 90 bottom
RC78  0_0402_5%  [R0402_0OHM]  80.92 106.16 270 bottom
RC79  220_0402_5%  [R_0402]  80.04 106.16 270 bottom
RC80  0_0402_5%  [R0402_0OHM]  79.15 106.16 270 bottom
RC81  49.9_0402_1%  [R_0402]  77.24 106.03 270 bottom
RC82  10K_0201_5%  [R_0201]  60.38 104.57 90 bottom
RC83  1K_0201_5%  [R_0201]  82.32 104.46 90 bottom
RC84  51_0402_5%  [R_0402]  74.85 105.2 0 bottom
RC85  2.2K_0201_5%  [R_0201]  54.13 105.12 0 bottom
RC86  0_0201_5%  [R_0201]  73.66 105.31 270 bottom
RC87  10K_0201_5%  [R_0201]  59.82 105.16 270 bottom
RC88  10K_0201_5%  [R_0201]  58.58 104.56 180 bottom
RC89  2.2K_0201_5%  [R_0201]  54.13 104.56 0 bottom
RC90  56_0201_5%  [R_0201]  80.17 104.51 0 bottom
RC91  0_0603_5%  [R0603_0OHM]  67.74 103.76 90 bottom
RC92  0_0201_5%  [R_0201]  75.35 104.43 180 bottom
RC93  51_0402_5%  [R_0402]  76.99 104.26 180 bottom
RC94  51_0402_5%  [R_0402]  91.47 104.61 270 bottom
RC95  51_0402_5%  [R_0402]  90.58 104.61 270 bottom
RC96  100_0201_1%  [R_0201]  80.76 103.93 180 bottom
RC97  51_0402_5%  [R_0402]  93.73 104.36 270 bottom
RC98  51_0402_5%  [R_0402]  92.84 104.36 270 bottom
RC99  0_0603_5%  [R0603_0OHM]  64.07 103.1 90 bottom
RC100  0_0201_5%  [R_0201]  78.98 103.77 0 bottom
RC101  0_0201_5%  [R_0201]  77.74 103.77 0 bottom
RC102  0_0603_5%  [R0603_0OHM]  62.84 103.04 90 bottom
RC103  0_0402_5%  [R_0402]  88.42 103.65 0 bottom
RC104  51_0402_5%  [R_0402]  76.99 103.37 180 bottom
RC105  0_0201_5%  [R_0201]  79.59 103.19 180 bottom
RC106  0_0201_5%  [R_0201]  77.74 103.19 0 bottom
RC107  100K_0402_5%  [R_0402]  94.77 103.16 0 bottom
RC108  0_0603_5%  [R0603_0OHM]  65.3 102.47 90 bottom
RC109  0_0201_5%  [R_0201]  93.88 102.72 270 bottom
RC110  0_0201_5%  [R_0201]  93.29 102.72 270 bottom
RC111  0_0201_5%  [R_0201]  92.71 102.72 270 bottom
RC112  49.9K_0201_1%  [R_0201]  48.01 102.06 90 bottom
RC113  10K_0201_5%  [R_0201]  47.37 102.06 90 bottom
RC114  1K_0402_5%  [R_0402]  90.22 102.68 270 bottom
RC115  0_0201_5%  [R_0201]  91.49 102.49 270 bottom
RC116  0_0201_5%  [R_0201]  90.93 102.49 270 bottom
RC117  499_0402_1%  [R_0402]  80.97 102.48 270 bottom
RC118  1K_0402_5%  [R_0402]  80.06 101.56 90 bottom
RC119  51_0402_5%  [R_0402]  79.15 101.56 90 bottom
RC120  51_0402_5%  [R_0402]  77.88 101.56 90 bottom
RC121  0_0201_5%  [R_0201]  87.11 101.97 0 bottom
RC122  1K_0201_5%  [R_0201]  86.51 101.98 270 bottom
RC123  51_0402_5%  [R_0402]  75.89 101.77 270 bottom
RC124  2.2K_0201_5%  [R_0201]  61.85 101.05 180 bottom
RC125  0_0201_5%  [R_0201]  82.47 101.3 270 bottom
RC126  0_0201_5%  [R_0201]  81.89 101.3 270 bottom
RC127  1K_0201_5%  [R_0201]  79.13 100.62 180 bottom
RC128  2.2K_0201_5%  [R_0201]  61.85 100.48 180 bottom
RH1  2.2K_0201_5%  [R_0201]  117.07 132.08 0 top
RH2  2.2K_0201_5%  [R_0201]  117.07 131.45 0 top
RH3  33_0201_1%  [R_0201]  52.82 131.1 0 top
RH4  33_0201_1%  [R_0201]  55.23 131.1 0 top
RH5  33_0201_1%  [R_0201]  55.23 130.55 0 top
RH6  2.2K_0201_5%  [R_0201]  124.62 130.25 180 top
RH7  1M_0402_5%  [R_0402]  46.84 129.96 0 top
RH8  33_0201_1%  [R_0201]  54.17 129.94 0 top
RH9  100K_0201_5%  [R_0201]  48.54 129.92 270 top
RH10  2.2K_0201_5%  [R_0201]  123.41 129.47 180 top
RH11  1K_0201_5%  [R_0201]  53.15 129.35 0 top
RH12  2.2K_0201_5%  [R_0201]  125.48 129.16 270 top
RH13  2.2K_0201_5%  [R_0201]  126.03 129.16 270 top
RH14  0_0201_5%  [R0201_0OHM]  53.73 128.77 180 top
RH15  10K_0201_5%  [R_0201]  54.93 128.77 180 top
RH16  0_0402_5%  [R0402_0OHM]  45.92 128.18 0 top
RH17  1K_0201_5%  [R_0201]  54.93 128.18 180 top
RH18  0_0402_5%  [R0402_0OHM]  52.7 128.03 0 top
RH19  0_0402_5%  [R_0402]  47.7 127.27 90 top
RH20  2.2K_0201_5%  [R_0201]  54.93 127.6 180 top
RH21  0_0402_5%  [R0402_0OHM]  45.92 127.29 0 top
RH22  0_0201_5%  [R0201_0OHM]  53.71 127.29 180 top
RH23  20K_0201_5%  [R_0201]  56.55 127.65 0 top
RH24  10K_0201_5%  [R_0201]  46.55 126.53 180 top
RH25  20K_0201_5%  [R_0201]  56.16 126.91 180 top
RH26  0_0402_5%  [R0402_0OHM]  55.88 124.5 180 top
RH27  22_0201_5%  [R_0201]  56.69 123.41 90 top
RH29  10K_0201_5%  [R_0201]  45.19 121.2 180 top
RH30  10K_0201_5%  [R_0201]  46.63 121.2 180 top
RH31  10K_0201_5%  [R_0201]  45.19 120.31 180 top
RH32  10K_0201_5%  [R_0201]  46.63 120.31 180 top
RH33  10K_0201_5%  [R_0201]  53.43 119.83 0 top
RH34  10K_0201_5%  [R_0201]  45.19 119.42 180 top
RH35  10K_0201_5%  [R_0201]  46.63 119.42 180 top
RH36  10K_0201_5%  [R_0201]  54.01 119.22 180 top
RH38  10K_0201_5%  [R_0201]  45.4 117.99 180 top
RH39  100K_0201_5%  [R_0201]  45.48 117.41 180 top
RH40  100K_0402_5%  [R_0402]  53.37 116.47 180 top
RH41  10K_0201_5%  [R_0201]  48.21 116.49 90 top
RH42  10K_0201_5%  [R_0201]  48.79 116.49 90 top
RH43  10K_0201_5%  [R_0201]  49.38 117.06 270 top
RH44  10K_0201_5%  [R_0201]  49.96 117.06 270 top
RH45  100K_0402_5%  [R_0402]  50.93 116.02 90 top
RH46  SHORT PADS  [SHORTPADS]  52.02 114.82 270 top
RH47  SHORT PADS  [SHORTPADS]  53.31 114.82 270 top
RH48  1K_0201_5%  [R_0201]  48.67 114.04 90 top
RH49  1K_0201_5%  [R_0201]  49.25 114.04 90 top
RH50  33_0201_1%  [R_0201]  49.83 114.04 90 top
RH51  33_0201_1%  [R_0201]  50.44 114.04 90 top
RH52  33_0201_1%  [R_0201]  51.03 114.04 90 top
RH53  499_0402_1%  [R_0402]  56.26 111.62 270 top
RH54  499_0402_1%  [R_0402]  57.15 111.62 270 top
RH55  33_0201_1%  [R_0201]  46.61 107.48 180 top
RH56  1K_0201_5%  [R_0201]  45.31 107.48 270 top
RH57  33_0201_1%  [R_0201]  46.61 106.87 180 top
RH58  10K_0201_5%  [R_0201]  50.48 129.86 0 bottom
RH59  10K_0201_5%  [R_0201]  50.48 129.28 0 bottom
RH60  10M_0402_5%  [R_0402]  56.24 129.68 270 bottom
RH61  10K_0201_5%  [R_0201]  49.85 129.15 180 bottom
RH62  1K_0201_5%  [R_0201]  50.48 128.69 0 bottom
RH63  8.2K_0201_5%  [R_0201]  49.47 128.54 180 bottom
RH64  100K_0201_5%  [R_0201]  56.34 128.04 270 bottom
RH65  8.2K_0201_5%  [R_0201]  49.45 127.36 90 bottom
RH66  10K_0201_5%  [R_0201]  48.87 127.94 270 bottom
RH67  100K_0201_5%  [R_0201]  48.13 127.35 90 bottom
RH68  0_0402_5%  [R0402_0OHM]  55.6 126.43 180 bottom
RH69  22_0201_5%  [R_0201]  56.93 126.18 180 bottom
RH70  10K_0201_5%  [R_0201]  53.62 126.29 270 bottom
RH71  0_0402_5%  [R0402_0OHM]  52.88 125.95 180 bottom
RH72  100K_0201_5%  [R_0201]  55.74 125.69 180 bottom
RH73  10K_0201_5%  [R_0201]  47.56 125.93 270 bottom
RH74  0_0402_5%  [R0402_0OHM]  56.46 125.39 0 bottom
RH75  100K_0201_5%  [R_0201]  54.51 125.1 90 bottom
RH76  100K_0201_5%  [R_0201]  55.74 125.11 180 bottom
RH77  0_0402_5%  [R0402_0OHM]  51.97 125.06 0 bottom
RH78  0_0402_5%  [R_0402]  53.77 124.98 270 bottom
RH79  0_0402_5%  [R0402_0OHM]  51.87 124.17 0 bottom
RH80  150K_0201_5%  [R_0201]  49.33 124.15 0 bottom
RH81  47K_0201_5%  [R_0201]  48.07 124.15 270 bottom
RH82  0_0201_5%  [R_0201]  47.51 123.57 90 bottom
RH83  150K_0201_5%  [R_0201]  49.86 123.57 180 bottom
RH85  1K_0201_5%  [R_0201]  55.08 122.11 180 bottom
RH86  1K_0201_5%  [R_0201]  55.02 119.51 270 bottom
RH87  100K_0201_5%  [R_0201]  55.7 117.71 90 bottom
RH88  10K_0201_5%  [R_0201]  55.09 117.71 90 bottom
RH89  100K_0201_5%  [R_0201]  54.25 116.88 0 bottom
RH90  10K_0201_5%  [R_0201]  53.85 116.3 270 bottom
RH91  100K_0201_5%  [R_0201]  53.26 115.71 90 bottom
RH92  33_0201_1%  [R_0201]  50.86 115.84 180 bottom
RH93  33_0201_1%  [R_0201]  49.11 115.84 0 bottom
RH94  33_0201_1%  [R_0201]  47.69 115.84 0 bottom
RH95  1K_0201_5%  [R_0201]  54.86 113.16 90 bottom
RH96  10K_0201_5%  [R_0201]  54.28 113.16 90 bottom
RH97  1K_0201_5%  [R_0201]  53.72 113.16 90 bottom
RH98  2.2K_0201_5%  [R_0201]  53.14 113.74 270 bottom
RH99  10K_0201_5%  [R_0201]  56.07 112.97 180 bottom
RH100  10K_0201_5%  [R_0201]  54.43 111.76 90 bottom
RH101  1K_0201_5%  [R_0201]  55.57 111.69 90 bottom
RH102  1K_0201_5%  [R_0201]  55.02 111.69 90 bottom
RH103  2.7K_0201_1%  [R_0201]  57.14 111.52 180 bottom
RH104  1M_0402_1%  [R_0402]  57.38 109.69 90 bottom
RH105  10K_0201_5%  [R_0201]  39.22 109.55 270 bottom
RH106  10K_0201_5%  [R_0201]  56.38 107.5 0 bottom
RH107  10K_0201_5%  [R_0201]  82.92 107.23 180 bottom
RH108  1K_0201_5%  [R_0201]  86.12 106 90 bottom
RH109  10K_0201_5%  [R_0201]  62.61 106.38 270 bottom
RH110  10K_0201_5%  [R_0201]  60.07 106.35 270 bottom
RH111  0_0402_5%  [R0402_0OHM]  54.74 105.91 0 bottom
RH112  33_0201_1%  [R_0201]  49.16 105.88 180 bottom
RH113  33_0201_1%  [R_0201]  47.38 105.88 0 bottom
RH114  1K_0201_5%  [R_0201]  52.79 105.32 0 bottom
RH115  10K_0201_5%  [R_0201]  62.01 105.2 0 bottom
RH116  10K_0201_5%  [R_0201]  58 105.17 0 bottom
RH117  1K_0201_5%  [R_0201]  48.63 104.97 0 bottom
RH118  10K_0201_5%  [R_0201]  60.93 105.18 90 bottom
RH119  10K_0201_5%  [R_0201]  59.26 104.57 90 bottom
RH120  1K_0201_5%  [R_0201]  52.79 104.74 0 bottom
RH121  0_0201_5%  [R0201_0OHM]  68.73 104.69 0 bottom
RH122  10K_0201_5%  [R_0201]  51.22 104.66 180 bottom
RH123  1K_0201_5%  [R_0201]  48.63 104.38 0 bottom
RH124  10K_0201_5%  [R_0201]  52.79 104.16 0 bottom
RH125  0_0201_5%  [R0201_0OHM]  68.73 104.13 0 bottom
RH126  10K_0201_5%  [R_0201]  50.57 104.05 180 bottom
RH127  100K_0201_5%  [R_0201]  48.63 103.8 0 bottom
RH128  10K_0201_5%  [R_0201]  49.99 103.47 0 bottom
RH129  100K_0201_5%  [R_0201]  51.54 103.56 270 bottom
RH130  10K_0201_5%  [R_0201]  48.63 103.22 0 bottom
RH131  2.2K_0201_5%  [R_0201]  48.63 102.63 0 bottom
RH132  2.2K_0201_5%  [R_0201]  48.63 102.05 0 bottom
RH133  0_0201_5%  [R0201_0OHM]  61.94 104.02 90 bottom
RTCD1  -  [BAT54HT1G_SOD323-2]  26.5 18.2 0 bottom
RTCR1  1.2K_0402_5%  [R_0402]  24.92 18.86 90 bottom
RV1  10K_0201_5%  [R_0201]  119.24 113.32 0 top
RV2  10K_0201_5%  [R_0201]  119.24 112.77 0 top
RV3  10K_0201_5%  [R_0201]  130.2 112.6 270 top
RV4  10K_0201_5%  [R_0201]  119.24 111.32 0 top
RV5  0_0201_5%  [R0201_0OHM]  130.8 111.37 180 top
RV6  10K_0201_5%  [R_0201]  119.24 110.76 0 top
RV7  0_0201_5%  [R0201_0OHM]  130.8 110.76 180 top
RV8  10K_0201_5%  [R_0201]  119.24 110.2 0 top
RV9  10K_0201_5%  [R_0201]  119.24 109.64 0 top
RV10  10K_0201_5%  [R_0201]  119.24 109.08 0 top
RV11  10K_0201_5%  [R_0201]  119.24 108.52 0 top
RV12  100K_0201_5%  [R_0201]  130.2 107.8 90 top
RV13  4.99K_0201_1%  [R_0201]  119.77 107.84 180 top
RV14  100K_0201_5%  [R_0201]  130.2 107.19 270 top
RV15  1M_0201_5%  [R_0201]  119.77 106.82 180 top
RV16  0_0201_5%  [R0201_0OHM]  119.76 106.21 180 top
RV17  1M_0201_5%  [R_0201]  119.76 105.6 180 top
RV18  10K_0402_5%  [R_0402]  22.02 58.02 270 top
RV19  10K_0402_5%  [R_0402]  22.02 59.77 270 top
RV20  1M_0201_5%  [R_0201]  22.59 49.53 180 top
RV21  1M_0201_5%  [R_0201]  22.59 50.12 180 top
RV22  4.99K_0201_1%  [R_0201]  22.62 51.41 180 top
RV23  10K_0402_5%  [R_0402]  23.04 58.02 270 top
RV24  10K_0402_5%  [R_0402]  23.04 59.77 270 top
RV25  10K_0402_5%  [R_0402]  24.03 58.02 270 top
RV26  10K_0402_5%  [R_0402]  24.03 59.77 270 top
RV27  10K_0402_5%  [R_0402]  27.89 58.55 0 top
RV28  10K_0402_5%  [R_0402]  27.89 59.48 0 top
RV29  10K_0201_5%  [R_0201]  33.39 54.28 180 top
RV30  100K_0201_5%  [R_0201]  32.85 49.89 0 top
RV31  100K_0201_5%  [R_0201]  32.85 50.45 0 top
RX1  2.2K_0402_5%  [R_0402]  18.31 56.2 0 bottom
RX2  2.2K_0402_5%  [R_0402]  18.31 55.34 0 bottom
RX3  10K_0402_5%  [R_0402]  19.33 53.05 180 bottom
RZ1  10K_0402_5%  [R_0402]  197.87 104.59 270 top
RZ2  10K_0402_5%  [R_0402]  196.96 102.81 0 top
RZ3  1M_0402_5%  [R_0402]  192.94 98.97 90 top
SW1  TAFG3-12WQR_3P  [SW_TAFG3-12WQR_3P]  4.33 140.15 270 top
SW2  TAFG3-12WQR_3P  [SW_TAFG3-12WQR_3P]  4.33 128.8 270 top
SW3  TS-A52-3-P1-S017_4P  [SW_TS-A52-3-P1-S017_4P]  180.98 99.42 0 bottom
T1  PAD~D  [TPC12]  211.4 136.97 0 top
T2  PAD~D  [TPC12]  211.48 136.46 0 top
T3  PAD~D  [TPC12]  204 134.13 0 top
T4  PAD~D  [TPC12]  201.94 133.95 0 top
T5  PAD~D  [TPC12]  62.79 132.73 0 top
T6  PAD~D  [TPC12]  203.73 132.7 0 top
T7  PAD~D  [TPC12]  202.16 132.67 0 top
T8  PAD~D  [TPC12]  62 130.8 0 top
T9  PAD~D  [TPC12]  52.43 128.79 0 top
T10  PAD~D  [TPC12]  45.21 128.41 0 top
T11  PAD~D  [TPC12]  52.5 127.27 0 top
T12  PAD~D  [TPC12]  45.08 125.92 0 top
T13  PAD~D  [TPC12]  54.89 125.49 0 top
T14  PAD~D  [TPC12]  198.03 105.78 0 top
T15  PAD~D  [TPC12]  51.64 129.94 180 bottom
T16  PAD~D  [TPC12]  49.96 129.94 180 bottom
T17  PAD~D  [TPC12]  51.61 129.02 180 bottom
T18  PAD~D  [TPC12]  51.18 128.08 180 bottom
T19  PAD~D  [TPC12]  50 127.28 180 bottom
T20  PAD~D  [TPC12]  57.66 126.57 180 bottom
T21  PAD~D  [TPC12]  52.83 123.46 180 bottom
T22  PAD~D  [TPC12]  57.61 123.36 180 bottom
T25  PAD~D  [TPC12]  92.63 109.25 180 bottom
T27  PAD~D  [TPC12]  39.75 108.98 180 bottom
T29  PAD~D  [TPC12]  83.87 106.49 180 bottom
T30  PAD~D  [TPC12]  59.56 106.44 180 bottom
T31  PAD~D  [TPC12]  63.17 105.45 180 bottom
T32  PAD~D  [TPC12]  51.26 105.2 180 bottom
T33  PAD~D  [TPC12]  61.24 104.61 180 bottom
T34  PAD~D  [TPC12]  56.21 104.13 180 bottom
T35  PAD~D  [TPC12]  51.13 104.1 180 bottom
T36  PAD~D  [TPC12]  77.37 100.68 180 bottom
T37  PAD~D  [TPC12]  76.58 100.65 180 bottom
TC1  PAD~D  [TPC12]  64.43 123.93 0 top
TC2  PAD~D  [TPC12]  48.67 123.48 0 top
TC3  PAD~D  [TPC12]  64.44 121.76 0 top
TC4  PAD~D  [TPC12]  63.31 114.33 0 top
TC5  PAD~D  [TPC12]  63.9 114.32 0 top
TC6  PAD~D  [TPC12]  62.22 112.12 0 top
TC7  PAD~D  [TPC12]  61.73 111.39 0 top
TC8  PAD~D  [TPC12]  42.46 105.43 0 top
TC9  PAD~D  [TPC12]  43.78 105.95 0 top
TC10  PAD~D  [TPC12]  44.75 106.82 0 top
TC11  PAD~D  [TPC12]  52.06 105.26 0 top
TC12  PAD~D  [TPC12]  53.23 103.63 0 top
TC13  PAD~D  [TPC12]  52.65 103.61 0 top
TC14  PAD~D  [TPC12]  35.36 85.51 0 top
TC15  PAD~D  [TPC12]  43.97 53.33 0 top
TC16  PAD~D  [TPC12]  43.94 52.09 270 top
TC17  PAD~D  [TPC12]  35.9 50.51 0 top
TC18  PAD~D  [TPC12]  36.83 50.51 0 top
TC19  PAD~D  [TPC12]  40.46 50.46 0 top
TC20  PAD~D  [TPC12]  41 44.9 0 top
TC21  PAD~D  [TPC12]  41 45.35 0 top
TC22  PAD~D  [TPC12]  33.31 42.4 0 top
TC23  PAD~D  [TPC12]  38.53 34.38 0 top
TC25  PAD~D  [TPC12]  21.08 131.74 180 bottom
TC26  PAD~D  [TPC12]  22.1 131.71 180 bottom
TC27  PAD~D  [TPC12]  22.35 130.98 180 bottom
TC28  PAD~D  [TPC12]  22.35 130.42 180 bottom
TC29  PAD~D  [TPC12]  60.73 127.55 180 bottom
TC30  PAD~D  [TPC12]  58.72 127.52 180 bottom
TC31  PAD~D  [TPC12]  47.6 126.81 180 bottom
TC32  PAD~D  [TPC12]  57.58 124.73 180 bottom
TC33  PAD~D  [TPC12]  56.84 124.73 180 bottom
TC34  PAD~D  [TPC12]  57.58 124.17 180 bottom
TC35  PAD~D  [TPC12]  51.16 123.64 180 bottom
TC36  PAD~D  [TPC12]  51.74 123.54 180 bottom
TC37  PAD~D  [TPC12]  53.97 123.43 180 bottom
TC38  PAD~D  [TPC12]  53.54 123.43 180 bottom
TC39  PAD~D  [TPC12]  57.61 122.95 180 bottom
TC40  PAD~D  [TPC12]  82.12 122.05 180 bottom
TC41  PAD~D  [TPC12]  58.62 121.54 180 bottom
TC42  PAD~D  [TPC12]  55.19 121.44 180 bottom
TC43  PAD~D  [TPC12]  55.09 120.72 180 bottom
TC44  PAD~D  [TPC12]  56.44 118.35 180 bottom
TC45  PAD~D  [TPC12]  56.16 112.44 180 bottom
TC46  PAD~D  [TPC12]  56.06 111.6 180 bottom
TC47  PAD~D  [TPC12]  57.63 111.45 270 bottom
TC50  PAD~D  [TPC12]  86.23 108.42 180 bottom
TC53  PAD~D  [TPC12]  57.63 107.41 180 bottom
TC54  PAD~D  [TPC12]  65.1 107.33 180 bottom
TC55  PAD~D  [TPC12]  83.51 107.23 180 bottom
TC56  PAD~D  [TPC12]  72.82 106.95 180 bottom
TC57  PAD~D  [TPC12]  72.08 106.95 180 bottom
TC58  PAD~D  [TPC12]  57.63 106.9 180 bottom
TC59  PAD~D  [TPC12]  65.1 106.62 180 bottom
TC60  PAD~D  [TPC12]  56.92 106.57 180 bottom
TC61  PAD~D  [TPC12]  60.58 106.44 180 bottom
TC62  PAD~D  [TPC12]  58.62 106.44 180 bottom
TC63  PAD~D  [TPC12]  63.17 106.42 180 bottom
TC64  PAD~D  [TPC12]  81.69 106.34 180 bottom
TC65  PAD~D  [TPC12]  78.38 106.21 180 bottom
TC66  PAD~D  [TPC12]  76.35 106.09 180 bottom
TC67  PAD~D  [TPC12]  56.24 106.09 180 bottom
TC68  PAD~D  [TPC12]  59.56 105.83 180 bottom
TC69  PAD~D  [TPC12]  58.83 105.83 180 bottom
TC70  PAD~D  [TPC12]  56.95 105.83 180 bottom
TC71  PAD~D  [TPC12]  56.64 105.3 180 bottom
TC72  PAD~D  [TPC12]  55.93 105.3 180 bottom
TC73  PAD~D  [TPC12]  57.45 104.51 180 bottom
TC74  PAD~D  [TPC12]  47.38 103.52 180 bottom
TC75  PAD~D  [TPC12]  68.96 102.86 180 bottom
TC76  PAD~D  [TPC12]  67.84 101.62 180 bottom
TC77  PAD~D  [TPC12]  67.82 100.9 180 bottom
TC78  PAD~D  [TPC12]  64.44 122.32 0 top
TC79  PAD~D  [TPC12]  63.33 117.45 0 top
TC80  PAD~D  [TPC12]  63.84 116.88 0 top
TC81  PAD~D  [TPC12]  63.33 116.56 0 top
TC82  PAD~D  [TPC12]  64.41 122.85 0 top
TC83  PAD~D  [TPC12]  64.41 123.36 0 top
TC84  PAD~D  [TPC12]  62.06 121.77 0 top
U1  -  [G601A31U_ADFN6_1P5X1P5]  197.84 139.04 0 top
U2  -  [NPCT650JAAYX_QFN32_5X5]  56.06 136.77 180 top
U3  -  [APE8937GN2_DFN8_2X2]  47.55 136.11 0 top
U4  -  [SN74AVC4T774_UQFN16_2P6X1P8]  46.84 134.13 180 top
U5  -  [NL17SZ14DFT2G_SOT353-5]  25.96 127.91 0 top
U6  TPS68470YFFR_DSBGA56  [TPS68470YFFR_DSBGA_56P]  130.56 126.58 180 top
U7  -  [EM5209VF_DFN14_3X2]  109.1 128.93 180 top
U8  -  [SN74AHC1G08DCKR_SC70-5]  49.14 128.2 270 top
U9  -  [TPS79801QDGNRQ1_MSOP8]  144.13 128.38 180 top
U12  -  [EM5209VF_DFN14_3X2]  205.82 127.02 270 top
U13  -  [APE8937GN2_DFN8_2X2]  151.65 123.36 90 top
U14  -  [SN65LVPE501RGER_VQFN24_4X4]  212.54 117.71 180 top
U15  -  [EM5209VF_DFN14_3X2]  28.35 110.43 90 top
U16  W25Q64FVZPIQ_WSON8  [W25Q128FVPIQ_WSON8]  47.85 106.82 0 top
U17  -  [APE8937GN2_DFN8_2X2]  151.93 106.37 180 top
U18  -  [EM5209VF_DFN14_3X2]  217.22 105.22 180 top
U19  -  [SN74AHC1G08DCKR_SC70-5]  195.88 105.06 180 top
U20  -  [EM5209VF_DFN14_3X2]  34.32 103.02 0 top
U21  -  [TPA6132A2RTER_QFN16_3X3]  142.58 103.05 90 top
U22  -  [EM5209VF_DFN14_3X2]  49.87 102.22 90 top
U23  -  [MC74VHC1G32DFT2G_SC70-5]  78.97 101.87 180 top
U24  -  [MC74VHC1G32DFT2G_SC70-5]  74.37 101.69 270 top
U25  -  [PS8407ATQFN40GTR2A1_TQFN40_5X5]  30.64 73.25 90 top
U26  -  [APE8937GN2_DFN8_2X2]  41.18 71.48 90 top
U27  -  [PS8713BTQFN24GTR2_TQFN24_4X4]  36.95 62.77 270 top
U28  -  [W25Q80DVZPIG_WSON8]  36.86 55.86 270 top
U29  -  [TS3USB221ARSER_UQFN10_2X1P5]  24.05 63.65 90 top
U30  -  [SN74AHC1G08DCKR_SC70-5]  30.76 59.94 270 top
U31  -  [HD3SS460RHRR_QFN28_3P5X5P5]  23.01 37.56 0 top
U32  TPS65982_BGA96  [TPS65982_BGA_96P]  39.69 42.67 270 top
U33  EDFA164A2MA-GD-F_FBGA253  [EDFA164A1MA-GD-F_FBGA_253P]  69.78 131.78 90 bottom
U34  MEC1641-PZV_TFBGA144  [MEC1641-PZV_TFBGA_144P]  194.82 137.74 180 bottom
U35  EDFA164A2MA-GD-F_FBGA253  [EDFA164A1MA-GD-F_FBGA_253P]  84.89 123.79 0 bottom
U38  -  [NL17SZ14DFT2G_SOT353-5]  43.27 111.74 180 bottom
U39  -  [W25Q128FVPIQ_WSON8]  51.82 107.96 180 bottom
U41  -  [AP22850SH8-7_W-DFN2020-8]  113.96 108.1 90 bottom
U43  -  [SY6288C20AAC_SOT23-5]  179.84 106.23 180 bottom
U44  -  [NL17SZ14DFT2G_SOT353-5]  94.5 106.33 180 bottom
U45  -  [74AUP1G07GW_TSSOP5]  89.21 107.5 270 bottom
U46  -  [APE8937GN2_DFN8_2X2]  178.99 103.72 270 bottom
U47  -  [PS8338BQFN60GTR-A0_QFN60_5X9]  51.46 101.31 0 bottom
U48  -  [TPS22961DNYR_WSON8]  73.77 97.29 180 bottom
U49  -  [TPS22961DNYR_WSON8]  70.27 97.29 180 bottom
U50  -  [EM5209VF_DFN14_3X2]  66.4 97.4 180 bottom
U51  -  [NL17SZ14DFT2G_SOT353-5]  21 92.43 270 bottom
U52  -  [NL17SZ14DFT2G_SOT353-5]  212.18 109.88 90 top
UA1  -  [TS5A23157RSER_QFN10_2X1P5]  31.31 87.38 180 top
UA2  -  [ALC1006-CG_QFN48_6X6]  38.39 84.14 270 top
UA3  -  [ALC3266-CG_QFN56_7X7]  16.33 132.82 180 bottom
UC1  SKYLAKE_ULX_EDS/BGA  [SKL-Y-REV1P2_BGA_1515P-T]  60.61 109.43 0 bottom
UC2  -  [74AUP1G07GW_TSSOP5]  77.81 122.57 270 top
UH1  -  [SN74AHC1G08DCKR_SC70-5]  199.4 130.87 0 top
UH2  -  [SN74AHC1G08DCKR_SC70-5]  70.93 101.1 0 top
UH3  -  [SN74AHC1G08DCKR_SC70-5]  48.54 125.12 90 bottom
UH4  -  [SN74AHC1G08DCKR_SC70-5]  40.74 108.99 90 bottom
UH5  -  [SN74AHC1G08DCKR_SC70-5]  90.75 108.35 0 bottom
US1  -  [TPS2544RTER_WQFN16_3X3]  29.17 62.65 90 top
UV1  -  [PS8330BQFN48GTR2-A0_QFN48_7X7]  121.67 112.46 270 top
UV2  -  [PS8330BQFN48GTR2-A0_QFN48_7X7]  24.01 54.54 270 top
UV3  -  [APE8937GN2_DFN8_2X2]  19.24 59.79 0 bottom
